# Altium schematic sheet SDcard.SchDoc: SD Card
size A4; Date: Not used; ApprovedBy: Not used; CheckedBy: Not used; Author: Not used; CompanyName: STMicroelectronics; DrawnBy: Not used; Engineer: Not used; Organization: Not used; Address1: Not used; Address2: Not used; Address3: Not used; Address4: Not used; DocumentNumber: Not used; Revision: Not used; SheetNumber: 9; SheetTotal: 23
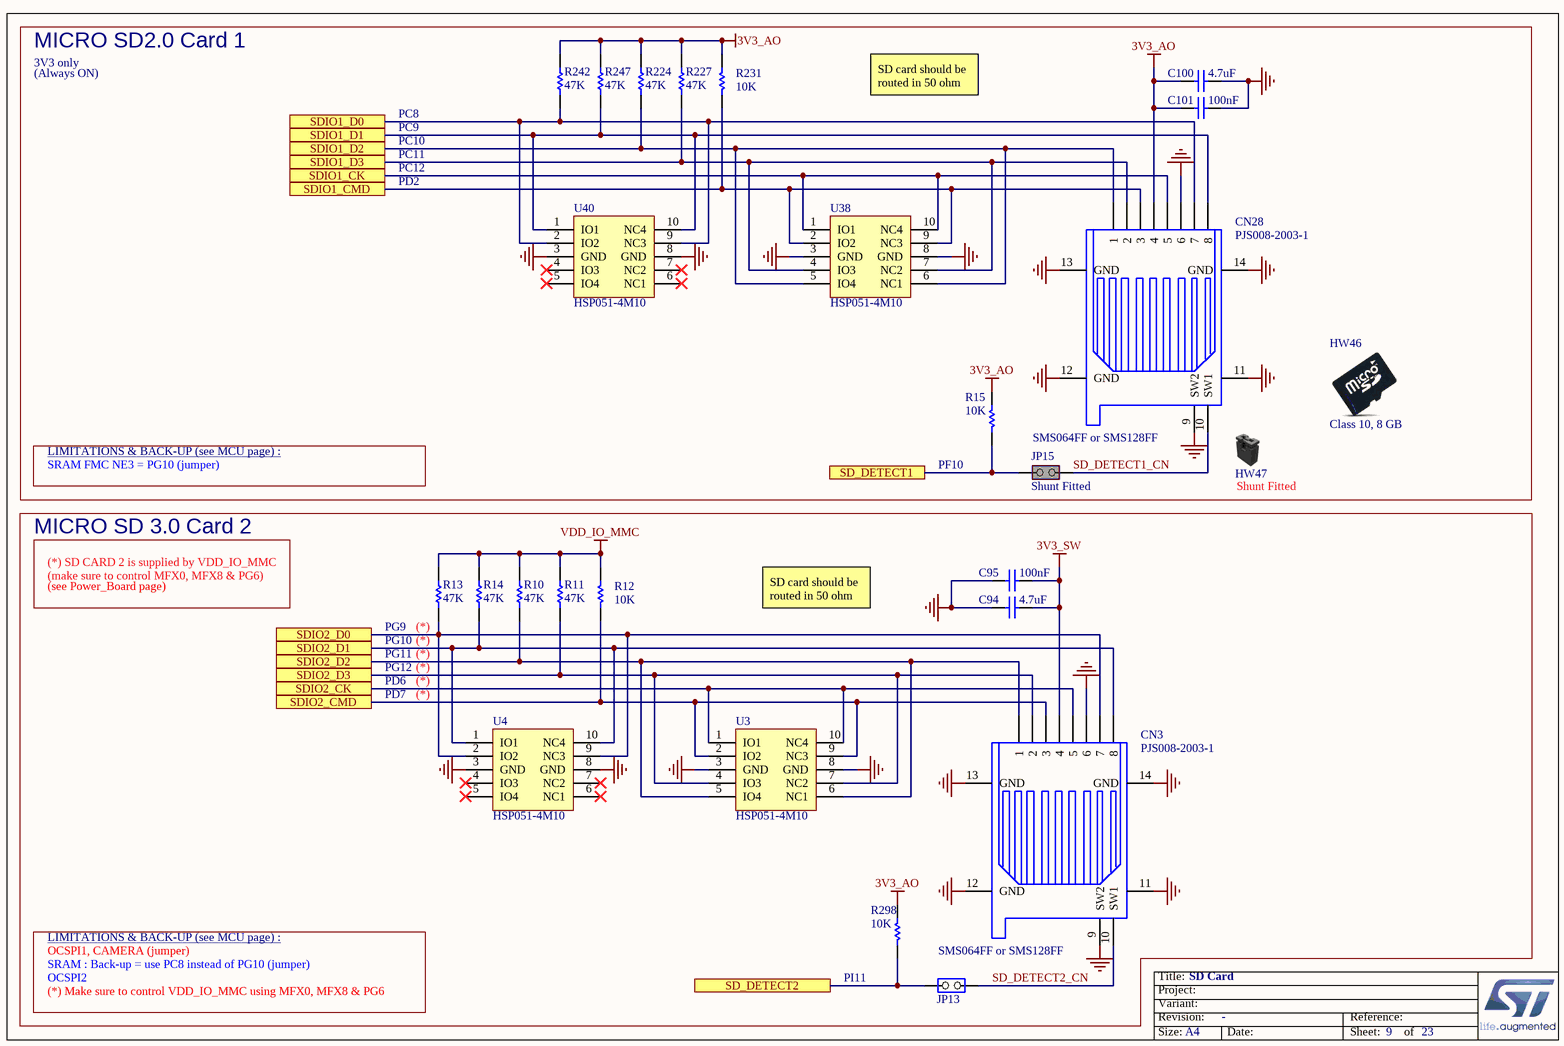
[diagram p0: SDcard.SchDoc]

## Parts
C94  value 4.7uF  [C0805]  (hidden comment: Capacitor)
C95  value 100nF  [C0402]  (hidden comment: Capacitor)
C100  value 4.7uF  [C0805]  (hidden comment: Capacitor)
C101  value 100nF  [C0402]  (hidden comment: Capacitor)
CN3  value PJS008-2003-1  [CON_MICROSD_YAMAICHI_PJS008-2003-1]  (hidden comment: microSD-PJS008-2003)
CN28  value PJS008-2003-1  [CON_MICROSD_YAMAICHI_PJS008-2003-1]  (hidden comment: microSD-PJS008-2003)
HW46  value Class 10, 8 GB  (hidden comment: Micro_SD_card)  (mechanical)
HW47  Shunt Black 2.54mm  (value not drawn)  (mechanical)
JP13  Jumper_Header 2x1  [CON_SAMTEC_TSW-102-07-G-S]  (value not drawn)
JP15  value Shunt Fitted  [CON_SAMTEC_TSW-102-07-G-S]  (hidden comment: Jumper_Header 2x1 Fitted)
R10  value 47K  [R0402]  (hidden comment: Resistor)
R11  value 47K  [R0402]  (hidden comment: Resistor)
R12  value 10K  [R0402]  (hidden comment: Resistor)
R13  value 47K  [R0402]  (hidden comment: Resistor)
R14  value 47K  [R0402]  (hidden comment: Resistor)
R15  value 10K  [R0402]  (hidden comment: Resistor)
R224  value 47K  [R0402]  (hidden comment: Resistor)
R227  value 47K  [R0402]  (hidden comment: Resistor)
R231  value 10K  [R0402]  (hidden comment: Resistor)
R242  value 47K  [R0402]  (hidden comment: Resistor)
R247  value 47K  [R0402]  (hidden comment: Resistor)
R298  value 10K  [R0402]  (hidden comment: Resistor)
U3  HSP051-4M10  [ESD_UQFN-10L_2P5X1_P050]
U4  HSP051-4M10  [ESD_UQFN-10L_2P5X1_P050]
U38  HSP051-4M10  [ESD_UQFN-10L_2P5X1_P050]
U40  HSP051-4M10  [ESD_UQFN-10L_2P5X1_P050]

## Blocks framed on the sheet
MICRO SD2.0 Card 1: C100 C101 CN28 HW46 HW47 JP15 R15 R224 R227 R231 R242 R247 U38 U40
MICRO SD 3.0 Card 2: C94 C95 CN3 JP13 R10-R14 R298 U3 U4

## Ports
SD_DETECT1, SD_DETECT2, SDIO1_CK, SDIO1_CMD, SDIO1_D0, SDIO1_D1, SDIO1_D2, SDIO1_D3, SDIO2_CK, SDIO2_CMD, SDIO2_D0, SDIO2_D1, SDIO2_D2, SDIO2_D3

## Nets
3V3_AO: C100.1 C101.1 CN28.4 R15.2 R224.2 R227.2 R231.2 R242.2 R247.2 R298.2
3V3_SW: C94.2 C95.2 CN3.4
GND: C94.1 C95.1 C100.2 C101.2 CN3.6 CN3.9(SW2) CN3.11(GND) CN3.12(GND) CN3.13(GND) CN3.14(GND) CN28.6 CN28.9(SW2) CN28.11(GND) CN28.12(GND) CN28.13(GND) CN28.14(GND) U3.3(GND) U3.8(GND) U4.3(GND) U4.8(GND) U38.3(GND) U38.8(GND) U40.3(GND) U40.8(GND)
VDD_IO_MMC: R10.2 R11.2 R12.2 R13.2 R14.2
SD_DETECT1: JP15.1(COMMON) R15.1 ; port SD_DETECT1
SD_DETECT1_CN: CN28.10(SW1) JP15.2(NO)
SD_DETECT2: JP13.2(NO) R298.1 ; port SD_DETECT2
SD_DETECT2_CN: CN3.10(SW1) JP13.1(COMMON)
SDIO1_CK: CN28.5 U38.1(IO1) U38.10(NC4) ; port SDIO1_CK
SDIO1_CMD: CN28.3 R231.1 U38.2(IO2) U38.9(NC3) ; port SDIO1_CMD
SDIO1_D0: CN28.7 R242.1 U40.2(IO2) U40.9(NC3) ; port SDIO1_D0
SDIO1_D1: CN28.8 R247.1 U40.1(IO1) U40.10(NC4) ; port SDIO1_D1
SDIO1_D2: CN28.1 R224.1 U38.5(IO4) U38.6(NC1) ; port SDIO1_D2
SDIO1_D3: CN28.2 R227.1 U38.4(IO3) U38.7(NC2) ; port SDIO1_D3
SDIO2_CK: CN3.5 U3.1(IO1) U3.10(NC4) ; port SDIO2_CK
SDIO2_CMD: CN3.3 R12.1 U3.2(IO2) U3.9(NC3) ; port SDIO2_CMD
SDIO2_D0: CN3.7 R13.1 U4.2(IO2) U4.9(NC3) ; port SDIO2_D0
SDIO2_D1: CN3.8 R14.1 U4.1(IO1) U4.10(NC4) ; port SDIO2_D1
SDIO2_D2: CN3.1 R10.1 U3.5(IO4) U3.6(NC1) ; port SDIO2_D2
SDIO2_D3: CN3.2 R11.1 U3.4(IO3) U3.7(NC2) ; port SDIO2_D3

Not connected (* = marked no-connect by the designer): U4 4(IO3)* 5(IO4)* 6(NC1)* 7(NC2)*; U40 4(IO3)* 5(IO4)* 6(NC1)* 7(NC2)*

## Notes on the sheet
- 3V3 only
- (Always ON)
- PC8
- SD card should be routed in 50 ohm
- PC9
- PC10
- PC11
- PD2
- PC12
- LIMITATIONS & BACK-UP (see MCU page) :
- SMS064FF or SMS128FF
- SRAM FMC NE3 = PG10 (jumper)
- (near R15) PF10
- (near HW47) Shunt Fitted
- (see Power_Board page)
- (*) SD CARD 2 is supplied by VDD_IO_MMC
  (make sure to control MFX0, MFX8 & PG6)
- (near R13) PG9
- (near R13) PG10
- (near R13) PG11
- (near R13) (*)
- (*)
- PG12
- PD6
- PD7
- SRAM : Back-up = use PC8 instead of PG10 (jumper)
- OCSPI1, CAMERA (jumper)
- OCSPI2
- (*) Make sure to control VDD_IO_MMC using MFX0, MFX8 & PG6
- (near R298) PI11

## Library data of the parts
C94 C100 = MCD-01974: Capacitor, MLCC, 4.7uF, 16V, 0805, X5R, 10%, T=1,25mm; Manufacturer_Part_Number: EMK212ABJ475KG-T; Manufacturer: TAIYO YUDEN; Alternate_Manufacturer_Part_Number: C0805C475K4PACTU; Alternate_Manufacturer: KEMET; Provided_By: SUBCO; ECCN_US: EAR99; ECCN_EU: NEC; Order_Code_RS: 691-1189
C95 C101 = MCD-00006: Capacitor, MLCC, 100nF, 16V, X7R, 10%, 0402, T=0.5mm; Manufacturer_Part_Number: CC0402KRX7R7BB104; Manufacturer: YAGEO; Alternate_Manufacturer_Part_Number: GCM155R71C104KA55D; Alternate_Manufacturer: MURATA; Provided_By: SUBCO; ECCN_US: EAR99; ECCN_EU: NEC
CN3 CN28 = MCD-00023: MicroSD Card Conn, Reversed-Type, Mnt Push-Push, Positionning holes; Part_Type: Connector; Manufacturer: YAMAICHI; Provided_By: SUBCO
HW46 = MCD-00673: 8GB microSDHC SD card Class 10; Part_Type: Misc; Manufacturer_Part_Number: TS8GUSDHC10; Manufacturer: TRANSCEND; Alternate_Manufacturer_Part_Number: SFSD8192N3BM1TO-I-GE-2B1-STD; Alternate_Manufacturer: SWISSBIT; Provided_By: SUBCO
HW47 = MCD-00043: SHUNT 2.54mm BLACK; Part_Type: Mechanical; Manufacturer: SAMTEC; Alternate_Manufacturer_Part_Number: 316102S111A; Alternate_Manufacturer: JIUBABA; Value: SNT-100-BK-G; Provided_By: SUBCO
JP13 = MCD-00045: Header, 2x1, 2,54mm, VR, TH, Height 5.84mm/2.54mm; Manufacturer_Part_Number: TSW-102-07-x-S; Manufacturer: SAMTEC; Part_Type: Connector; Alternate_Manufacturer_Part_Number: 313102S111116;313102S111116; Alternate_Manufacturer: JIUBABA; LIANYI; Value: Shunt not fitted; Provided_By: SUBCO
JP15 = MCD-00683: Header, 2x1, 2,54mm, VR, TH, Height 5.84mm/2.54mm - Shunt Fitted by default; Part_Type: Connector; Manufacturer_Part_Number: TSW-102-07-x-S; Manufacturer: SAMTEC; Alternate_Manufacturer_Part_Number: 313102S111116; Alternate_Manufacturer: LIANYI; Provided_By: SUBCO
R10 R11 R13 R14 R224 R227 R242 R247 = MCD-00063: Resistor,47K,0402,1%,1/16W; Manufacturer_Part_Number: RC0402FR-0747KL; Manufacturer: YAGEO; Provided_By: SUBCO; ECCN_US: EAR99; ECCN_EU: NEC
R12 R15 R231 R298 = MCD-00053: Resistor,10K,0402,1%,1/16W; Manufacturer_Part_Number: RC0402FR-0710KL; Manufacturer: YAGEO; Provided_By: SUBCO; ECCN_US: EAR99; ECCN_EU: NEC
U3 U4 U38 U40 = MCD-00667: 4-line ESD protection for high speed lines; Manufacturer: STMICROELECTRONICS; Part_Type: Diode; BMS_Part_Number: 9179041; Provided_By: SUBCO with ST control; ECCN_US: EAR99; ECCN_EU: NEC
